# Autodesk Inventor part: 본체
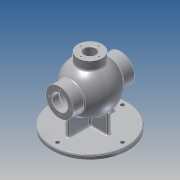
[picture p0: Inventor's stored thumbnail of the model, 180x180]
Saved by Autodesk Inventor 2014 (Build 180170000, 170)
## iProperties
Created: 2020-08
Part Number: 본체
Material: 알루미늄 6061
Document SubType Name: Modeling
Designer: kb542
Density: 2.71 g/cm^3
Appearance: 알루미늄 - 평지
Mass: 1759.17 g
Surface Area: 1342.42 cm^2
Volume: 649.142 cm^3
Author: kb542
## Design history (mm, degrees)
sketch "스케치1"
  geometry: L1 (-53, 0)-(53, 0); A1 r 53 centre (0, 0) between (53, 0) and (-53, 0); A2 r 43 centre (0, 0) between (43, 0) and (-43, 0); 2 further points
  constraints: 4 coincident, 4 point on circle, 4 point on line, 2 centre point, 2 end point, 1 horizontal, 1 midpoint
  dimensions: "d4" = 53 radius of A1; "d5" = 43 radius of A2
revolve "회전1" sketch "스케치1" stored, may be unused: angle "d2" = 90 deg
node "작업 평면2"
sketch "스케치2"
  geometry: C1 r 85 at (0, 0); 1 further point
  constraints: 1 centre point, 1 coincident
  dimensions: "d7" = 170 diameter of C1
extrude "돌출1" join sketch "스케치2" distance "d8" = 10; taper "d9" = 0 deg
node "작업 평면3"
sketch "스케치3"
  geometry: C1 r 31 at (0, 0); 1 further point
  constraints: 1 centre point, 1 coincident
  dimensions: "d11" = 62 diameter of C1
extrude "돌출2" join sketch "스케치3" stored distance "d12" = 10; taper "d13" = 0 deg
sketch "스케치4"
  geometry: C1 r 31 at (0, 0) reference; C2 r 17.5 at (0, 0)
  constraints: 1 centre point, 1 coincident
  dimensions: "d14" = 35 diameter of C2
extrude "돌출3" cut sketch "스케치4" distance "d15" = 16; taper "d16" = 0 deg
sketch "스케치5"
  geometry: C1 r 17.5 at (0, 0) reference; C2 r 18.5 at (0, 0)
  constraints: 1 centre point, 1 coincident
  dimensions: "d17" = 37 diameter of C2
extrude "돌출4" cut sketch "스케치5" distance "d18" = 1.75; taper "d19" = 0 deg
sketch "스케치6"
  geometry: C1 r 31 at (0, 0) reference; C2 r 17.5 at (0, 0)
  constraints: 1 centre point, 1 coincident
  dimensions: "d20" = 35 diameter of C2
extrude "돌출5" cut sketch "스케치6" stored distance "d21" = 1.75; taper "d22" = 0 deg
sketch "스케치7"
  geometry: C1 r 17.5 at (0, 0) reference; 1 further point
  constraints: 1 vertical alignment
  dimensions: "d23" = 24 distance of point (0, 24) C1.centre
hole "구멍1" sketch "스케치7" at (0, 24) diameter "d24" = 3.242; stored, may be unused: countersink angle "d28" = 90 deg, drill point angle "d30" = 118 deg; dims "d25" = 12, "d26" = 4, "d27" = 2, "d29" = 15
node "작업 평면4"
sketch "스케치8"
  geometry: C1 r 27 at (0, 0); 1 further point
  constraints: 1 centre point, 1 coincident
  dimensions: "d35" = 54 diameter of C1
extrude "돌출6" join sketch "스케치8" stored distance "d36" = 1.75; taper "d37" = 0 deg
sketch "스케치9"
  geometry: C1 r 27 at (0, 0) reference; C2 r 13 at (0, 0)
  constraints: 1 centre point, 1 coincident
  dimensions: "d38" = 26 diameter of C2
extrude "돌출7" cut sketch "스케치9" stored distance "d39" = 1.75; taper "d40" = 0 deg
chamfer "모따기1" distance "d41" = 1; stored, may be unused: second distance "d42" = 2, angle "d43" = 45 deg
sketch "스케치10"
  geometry: C1 r 27 at (0, 0) reference; 1 further point
  constraints: 1 vertical alignment
  dimensions: "d44" = 20 distance of point (0, 20) C1.centre
hole "구멍2" sketch "스케치10" at (0, 20) diameter "d45" = 3.242; stored, may be unused: countersink angle "d49" = 90 deg, drill point angle "d51" = 118 deg; dims "d46" = 12, "d47" = 4, "d48" = 2, "d50" = 15
sketch "스케치11"
  geometry: L1 (-4, -52)-(4, -52); L2 (4, -52)-(4, 52); L3 (4, 52)-(-4, 52); L4 (-4, 52)-(-4, -52); L5 (-4, -52)-(4, 52); L6 (4, -52)-(-4, 52); C1 r 85 at (0, 0) reference
  constraints: 12 end point, 2 midpoint, 2 parallel, 1 horizontal, 1 perpendicular
  dimensions: "d55" = 104 distance of L1.end L2.end; "d56" = 8 distance of L2.end L3.end
extrude "돌출8" join sketch "스케치11" stored distance "d57" = 1.75; taper "d58" = 0 deg
sketch "스케치12"
  geometry: L1 (43, -4)-(-43, -4); L2 (-43, -4)-(-43, 4); L3 (-43, 4)-(43, 4); L4 (43, 4)-(43, -4); L5 (43, -4)-(-43, 4); L6 (-43, -4)-(43, 4); C1 r 85 at (0, 0) reference
  constraints: 12 end point, 2 midpoint, 2 parallel, 1 horizontal, 1 perpendicular
  dimensions: "d59" = 86 distance of L2.end L3.end; "d60" = 8 distance of L1.end L2.end
extrude "돌출9" join sketch "스케치12" stored distance "d61" = 1.75; taper "d62" = 0 deg
node "작업 평면5"
sketch "스케치13"
  geometry: L1 (-27, 65)-(27, 65) reference; L2 (-27, 65)-(-27, 45.607) reference; 2 further points
  constraints: 1 other
  dimensions: "d64" = 9 distance from line of L1 point (0, 56); "d65" = 27 distance from line of point (0, 56) L2
feature "엠보싱1" sketch "스케치13" dims "d66" = 0.5, "d67" = 0
sketch "스케치14"
  geometry: C1 r 85 at (0, 0) reference; 1 further point
  constraints: 1 vertical alignment
  dimensions: "d68" = 72.5 distance of point (0, 72.5) C1.centre
hole "구멍3" sketch "스케치14" at (0, 72.5) diameter "d69" = 9; stored, may be unused: countersink angle "d73" = 90 deg, drill point angle "d75" = 118 deg; dims "d70" = 12, "d71" = 4, "d72" = 2, "d74" = 15
fillet "모깎기1" dims "d79" = 3
fillet "모깎기2" dims "d80" = 3
fillet "모깎기3" dims "d81" = 3
node "솔리드1"
mirror "대칭1"
pattern_circular "원형 패턴1" dims angle "d32" = 360 deg
mirror "대칭2"
pattern_circular "원형 패턴2" dims angle "d53" = 360 deg
pattern_circular "원형 패턴3" dims angle "d77" = 360 deg
other parameters: "d6" = -85, "d10" = -68, "d63" = -103
